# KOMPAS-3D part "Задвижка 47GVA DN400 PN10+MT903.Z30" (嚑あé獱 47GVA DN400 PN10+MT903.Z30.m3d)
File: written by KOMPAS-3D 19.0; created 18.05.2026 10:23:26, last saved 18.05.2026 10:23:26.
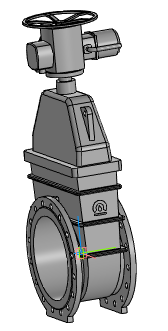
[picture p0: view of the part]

Document properties: Автор: Энергия; Полное имя файла: ..\Задвижка 47GVA DN50_DN1000+MT903.Z\Задвижка 47GVA DN400 PN10+MT903.Z30.a3d

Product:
- Part/product: Задвижка 47GVA DN400 PN10+MT903.Z30
    Масса: 685.322
  - Body: Электропривод MT903.Z20-30
      Масса: 83.2154
  - Body: Задвижка 47GVA DN400 PN10 без исполнительного механизма
      Масса: 602.107

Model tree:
1. Операция без истории:1
2. Операция без истории:2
